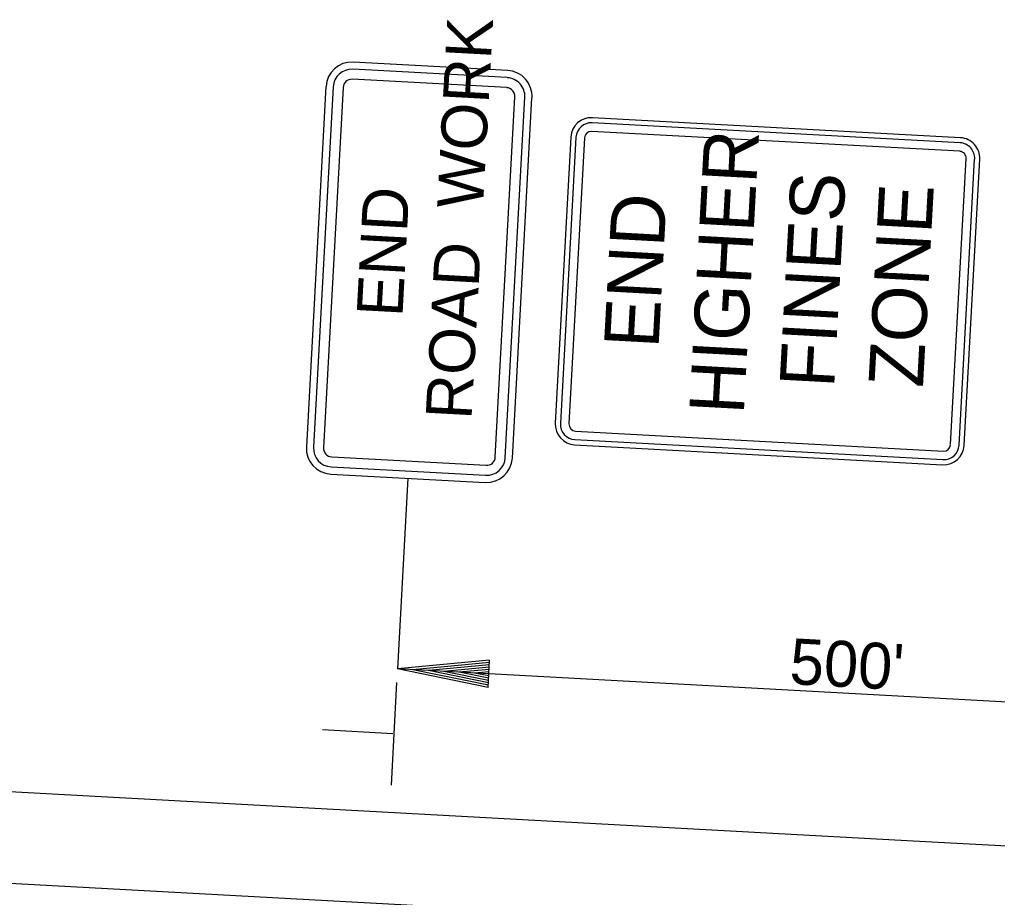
# Model space of a CAD drawing. Extents: x 879461 to 881100, y 1566470 to 1567598.
# Drawn here: x 879979.1 to 880107, y 1567234.9 to 1567349.8 of the extents above; entities that cross this region are included whole.
import ezdxf

# ---------------------------------------------------------------- set-up
doc = ezdxf.new("R2010")
doc.units = 0
for name, color, linetype in [('P_TC_Signs_Permanent', 7, 'Continuous'), ('P_TC_Signs_Temporary', 7, 'Continuous'), ('R_Draft', 7, 'Continuous')]:
    doc.layers.add(name, color=color, linetype=linetype)

msp = doc.modelspace()

# ---------------------------------------------------------------- linework, layer by layer
at = {"layer": 'P_TC_Signs_Permanent'}
for p, q in [((880102.17, 1567333.69), (880054, 1567336.31)), ((880102.2, 1567334.36), (880054.04, 1567336.98)), ((880102.11, 1567332.58), (880053.94, 1567335.19)), ((880051.22, 1567334.45), (880049.18, 1567296.99)), ((880051.89, 1567334.41), (880049.85, 1567296.95)), ((880053, 1567334.35), (880050.97, 1567296.89)), ((880100.91, 1567294.18), (880102.95, 1567331.63)), ((880102.03, 1567294.11), (880104.06, 1567331.57)), ((880102.7, 1567294.08), (880104.73, 1567331.54)), ((880051.75, 1567294.84), (880099.91, 1567292.22)), ((880051.81, 1567295.95), (880099.97, 1567293.33)), ((880051.71, 1567294.17), (880099.87, 1567291.55))]:
    msp.add_line(p, q, dxfattribs=at)
for centre, radius, start, end in [((880053.89, 1567334.3), 2.68, 86.8871, 176.8871), ((880053.89, 1567334.3), 2.01, 86.8871, 176.8871), ((880053.89, 1567334.3), 0.893, 86.8871, 176.8871), ((880102.06, 1567331.68), 2.01, 356.8871, 86.8871), ((880102.06, 1567331.68), 2.68, 356.8871, 86.8871), ((880102.06, 1567331.68), 0.893, 356.8871, 86.8871), ((880051.86, 1567296.84), 2.68, 176.8871, 266.8871), ((880051.86, 1567296.84), 2.01, 176.8871, 266.8871), ((880051.86, 1567296.84), 0.893, 176.8871, 266.8871), ((880100.02, 1567294.22), 2.68, 266.8871, 356.8871), ((880100.02, 1567294.22), 2.01, 266.8871, 356.8871), ((880100.02, 1567294.22), 0.893, 266.8871, 356.8871)]:
    msp.add_arc(centre, radius, start, end, dxfattribs=at)
at = {"layer": 'P_TC_Signs_Temporary'}
for p, q in [((880042.95, 1567343.15), (880022.73, 1567344.25)), ((880042.89, 1567342.22), (880022.67, 1567343.32)), ((880019.17, 1567341.07), (880016.61, 1567293.89)), ((880020.11, 1567341.01), (880017.54, 1567293.83)), ((880021.42, 1567340.94), (880018.85, 1567293.76)), ((880042.82, 1567340.91), (880022.6, 1567342.01)), ((880041.32, 1567292.54), (880043.89, 1567339.72)), ((880042.63, 1567292.47), (880045.2, 1567339.65)), ((880043.57, 1567292.42), (880046.13, 1567339.6)), ((880019.92, 1567292.58), (880040.14, 1567291.48)), ((880019.84, 1567291.27), (880040.06, 1567290.17)), ((880019.79, 1567290.33), (880040.01, 1567289.23))]:
    msp.add_line(p, q, dxfattribs=at)
for centre, radius, start, end in [((880022.54, 1567340.88), 3.37, 86.8871, 176.8871), ((880022.54, 1567340.88), 2.44, 86.8871, 176.8871), ((880042.76, 1567339.78), 2.44, 356.8871, 86.8871), ((880042.76, 1567339.78), 3.38, 356.8871, 86.8871), ((880022.54, 1567340.88), 1.13, 86.8871, 176.8871), ((880042.76, 1567339.78), 1.13, 356.8871, 86.8871), ((880019.98, 1567293.7), 3.38, 176.8871, 266.8871), ((880019.98, 1567293.7), 2.44, 176.8871, 266.8871), ((880019.98, 1567293.7), 1.13, 176.8871, 266.8871), ((880040.2, 1567292.6), 3.37, 266.8871, 356.8871), ((880040.2, 1567292.6), 2.44, 266.8871, 356.8871), ((880040.2, 1567292.6), 1.13, 266.8871, 356.8871)]:
    msp.add_arc(centre, radius, start, end, dxfattribs=at)
at = {"layer": 'R_Draft'}
for p, q in [((880029.9, 1567289.78), (880028.55, 1567264.82)), ((879664.27, 1567265.81), (880097.64, 1567242.24)), ((880040.59, 1567265.96), (880028.55, 1567264.82)), ((880040.58, 1567265.66), (880030.54, 1567264.71)), ((880040.4, 1567262.37), (880040.59, 1567265.96)), ((880150.74, 1567258.17), (880028.55, 1567264.82)), ((880040.4, 1567262.37), (880028.55, 1567264.82)), ((880040.42, 1567262.67), (880030.54, 1567264.71)), ((880040.56, 1567265.36), (880032.6, 1567264.6)), ((880040.43, 1567262.98), (880032.6, 1567264.6)), ((880040.55, 1567265.06), (880034.58, 1567264.49)), ((880040.45, 1567263.28), (880034.58, 1567264.49)), ((880040.53, 1567264.75), (880036.61, 1567264.38)), ((880040.47, 1567263.59), (880036.61, 1567264.38)), ((880040.51, 1567264.45), (880038.61, 1567264.27)), ((880040.48, 1567263.89), (880038.61, 1567264.27)), ((880027.73, 1567249.61), (880028.46, 1567263.06)), ((880027.9, 1567256.32), (880018.72, 1567256.82)), ((879663.62, 1567253.86), (880096.99, 1567230.29)), ((880097.64, 1567242.24), (880195.74, 1567236.91))]:
    msp.add_line(p, q, dxfattribs=at)

# ---------------------------------------------------------------- texts
at = {"layer": 'P_TC_Signs_Permanent'}
for s, p in [('HIGHER', (880073.84, 1567298.05)), ('FINES', (880085.66, 1567301.52)), ('ZONE', (880097.29, 1567301.57)), ('END', (880062.68, 1567306.7))]:
    msp.add_text(s, height=7.146, rotation=86.8871, dxfattribs=at).set_placement(p)
at = {"layer": 'P_TC_Signs_Temporary'}
for s, p in [('ROAD  WORK', (880038.2, 1567297.38)), ('END', (880029.17, 1567310.82))]:
    msp.add_text(s, height=6, rotation=86.8871, dxfattribs=at).set_placement(p)
at = {"layer": 'R_Draft'}
msp.add_text("500'", height=6, rotation=356.8871, dxfattribs=at).set_placement((880079.75, 1567262.85))

doc.saveas('drawing.dxf')
